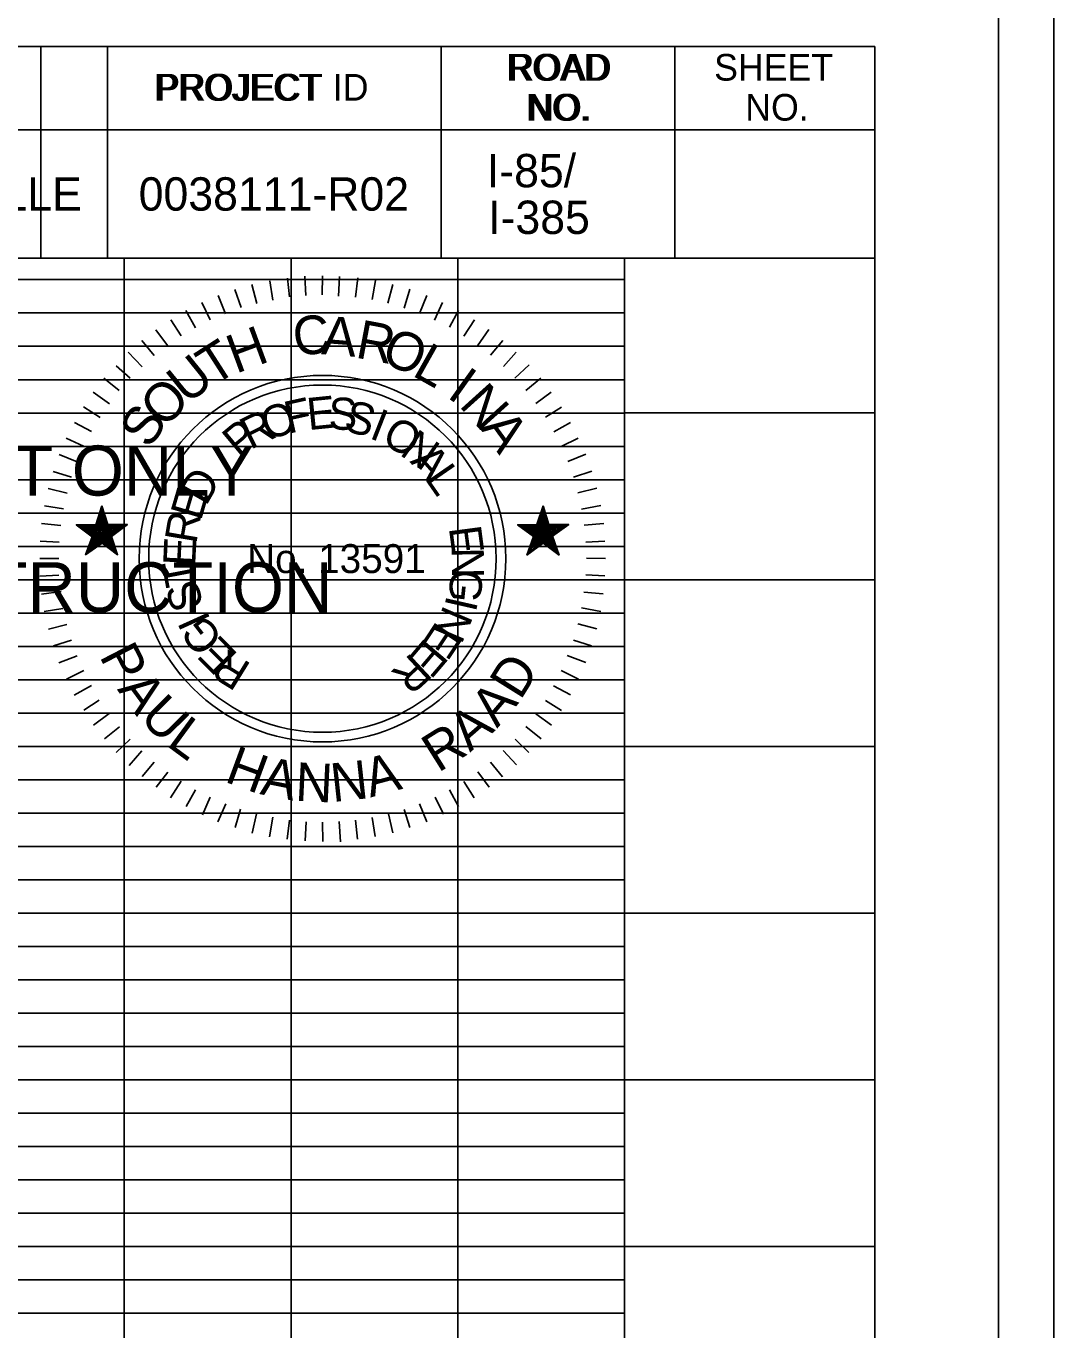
# Model space of a CAD drawing. Extents: x -3 to 42.6, y -1.4 to 22.8.
# Drawn here: x 30.206 to 33.287, y 16.75 to 20.66 of the extents above; entities that cross this region are included whole.
import ezdxf

# ---------------------------------------------------------------- set-up
doc = ezdxf.new("R2010")
doc.units = 0
for name, color, linetype in [('Level 1', 7, 'Continuous'), ('Level 2', 7, 'Continuous'), ('Level 3', 7, 'Continuous'), ('RD_SHT_Bndy', 7, 'Continuous'), ('RD_SHT_IplotShp', 7, 'Continuous'), ('RD_SHT_MjGrid', 7, 'Continuous'), ('RD_SHT_MnGrid', 7, 'Continuous'), ('RD_SHT_SEAL_DR', 7, 'Continuous'), ('RD_SHT_Snap', 7, 'Continuous'), ('RD_SHT_TX', 7, 'Continuous'), ('RD_Sketch10', 7, 'Continuous')]:
    doc.layers.add(name, color=color, linetype=linetype)

msp = doc.modelspace()

# ---------------------------------------------------------------- linework, layer by layer
at = {"layer": 'Level 1'}
for p, q in [((30.25, 20.5993), (30.25, 19.9643)), ((31.45, 20.5994), (31.45, 19.9644)), ((32.15, 20.5994), (32.15, 19.9644)), ((27.75, 20.3493), (32.75, 20.3494)), ((27.75, 19.9643), (32.75, 19.9644))]:
    msp.add_line(p, q, dxfattribs=at)
msp.add_lwpolyline([(-0.75, -0.4), (-0.75, 20.5995), (32.75, 20.5994), (32.7499, -0.4), (-0.75, -0.4)], dxfattribs=at)
at = {"layer": 'Level 2'}
for p, q in [((30.5, 0), (30.5, 19.9644)), ((31, 0), (31, 19.9644)), ((31.5, 0), (31.5, 19.9644)), ((32, 0), (32, 19.9644)), ((-0.75, 19), (32.75, 18.9999)), ((-0.75, 18), (32.75, 17.9999)), ((-0.75, 17), (32.75, 16.9999))]:
    msp.add_line(p, q, dxfattribs=at)
at = {"layer": 'Level 3'}
for p, q in [((0, 19.9), (32, 19.8999)), ((0, 19.8), (32, 19.7999)), ((0, 19.7), (32, 19.6999)), ((0, 19.6), (32, 19.5999)), ((0, 19.5), (32, 19.4999)), ((32, 19.5), (32.7499, 19.5)), ((0, 19.4), (32, 19.3999)), ((0, 19.3), (32, 19.2999)), ((0, 19.2), (32, 19.1999)), ((0, 19.1), (32, 19.0999)), ((0, 18.9), (32, 18.8999)), ((0, 18.8), (32, 18.7999)), ((0, 18.7), (32, 18.6999)), ((0, 18.6), (32, 18.5999)), ((0, 18.5), (32, 18.4999)), ((32, 18.5), (32.7499, 18.5)), ((0, 18.4), (32, 18.3999)), ((0, 18.3), (32, 18.2999)), ((0, 18.2), (32, 18.1999)), ((0, 18.1), (32, 18.0999)), ((0, 17.9), (32, 17.8999)), ((0, 17.8), (32, 17.7999)), ((0, 17.7), (32, 17.6999)), ((0, 17.6), (32, 17.5999)), ((0, 17.5), (32, 17.4999)), ((32, 17.5), (32.7499, 17.5)), ((0, 17.4), (32, 17.3999)), ((0, 17.3), (32, 17.2999)), ((0, 17.2), (32, 17.1999)), ((0, 17.1), (32, 17.0999)), ((0, 16.9), (32, 16.8999)), ((0, 16.8), (32, 16.7999))]:
    msp.add_line(p, q, dxfattribs=at)
at = {"layer": 'RD_SHT_Bndy'}
for p, q in [((30.45, 20.5994), (30.45, 19.9644)), ((31.45, 20.5994), (31.45, 19.9644)), ((32.15, 20.5994), (32.15, 19.9644)), ((28.85, 20.3493), (32.75, 20.3494)), ((28.85, 19.9643), (32.75, 19.9644))]:
    msp.add_line(p, q, dxfattribs=at)
msp.add_lwpolyline([(-0.75, -0.4), (-0.75, 20.5995), (32.75, 20.5994), (32.7499, -0.4), (-0.75, -0.4)], dxfattribs=at)
at = {"layer": 'RD_SHT_IplotShp'}
msp.add_lwpolyline([(-2.8793, 21.0836), (33.1207, 21.0836), (33.1207, -0.9164), (-2.8793, -0.9164)], close=True, dxfattribs=at)
at = {"layer": 'RD_SHT_MjGrid'}
for p, q in [((30.5, 0), (30.5, 19.9644)), ((31, 0), (31, 19.9644)), ((31.5, 0), (31.5, 19.9644)), ((32, 0), (32, 19.9644)), ((-0.75, 19), (32.75, 18.9999)), ((-0.75, 18), (32.75, 17.9999)), ((-0.75, 17), (32.75, 16.9999))]:
    msp.add_line(p, q, dxfattribs=at)
at = {"layer": 'RD_SHT_MnGrid'}
for p, q in [((0, 19.9), (32, 19.8999)), ((0, 19.8), (32, 19.7999)), ((0, 19.7), (32, 19.6999)), ((0, 19.6), (32, 19.5999)), ((0, 19.5), (32, 19.4999)), ((32, 19.5), (32.7499, 19.5)), ((0, 19.4), (32, 19.3999)), ((0, 19.3), (32, 19.2999)), ((0, 19.2), (32, 19.1999)), ((0, 19.1), (32, 19.0999)), ((0, 18.9), (32, 18.8999)), ((0, 18.8), (32, 18.7999)), ((0, 18.7), (32, 18.6999)), ((0, 18.6), (32, 18.5999)), ((0, 18.5), (32, 18.4999)), ((32, 18.5), (32.7499, 18.5)), ((0, 18.4), (32, 18.3999)), ((0, 18.3), (32, 18.2999)), ((0, 18.2), (32, 18.1999)), ((0, 18.1), (32, 18.0999)), ((0, 17.9), (32, 17.8999)), ((0, 17.8), (32, 17.7999)), ((0, 17.7), (32, 17.6999)), ((0, 17.6), (32, 17.5999)), ((0, 17.5), (32, 17.4999)), ((32, 17.5), (32.7499, 17.5)), ((0, 17.4), (32, 17.3999)), ((0, 17.3), (32, 17.2999)), ((0, 17.2), (32, 17.1999)), ((0, 17.1), (32, 17.0999)), ((0, 16.9), (32, 16.8999)), ((0, 16.8), (32, 16.7999))]:
    msp.add_line(p, q, dxfattribs=at)
at = {"layer": 'RD_SHT_SEAL_DR'}
for p, q in [((30.989, 19.9044), (30.9955, 19.8482)), ((31.0409, 19.9099), (31.0441, 19.8526)), ((31.0948, 19.9109), (31.0938, 19.8548)), ((31.1456, 19.9098), (31.1424, 19.8504)), ((31.2007, 19.9054), (31.1931, 19.8472)), ((30.8313, 19.8699), (30.8508, 19.8159)), ((30.8821, 19.885), (30.8972, 19.8288)), ((30.9361, 19.8968), (30.9458, 19.8385)), ((31.2536, 19.8969), (31.2428, 19.8407)), ((31.3055, 19.885), (31.2904, 19.8289)), ((31.3562, 19.8709), (31.3389, 19.8148)), ((30.7331, 19.8309), (30.7579, 19.7791)), ((30.7816, 19.8526), (30.8032, 19.7974)), ((31.407, 19.8526), (31.3854, 19.7986)), ((31.4545, 19.8309), (31.4296, 19.7781)), ((30.6845, 19.8073), (30.7136, 19.7554)), ((31.5021, 19.8073), (31.4751, 19.7575)), ((30.5948, 19.7489), (30.6294, 19.7024)), ((30.6401, 19.7791), (30.6704, 19.7316)), ((31.5496, 19.7791), (31.5182, 19.7305)), ((31.5928, 19.7499), (31.5593, 19.7014)), ((30.5527, 19.7175), (30.5894, 19.6722)), ((31.6348, 19.7176), (31.5981, 19.6733)), ((30.5116, 19.6819), (30.5537, 19.6388)), ((31.6748, 19.6819), (31.637, 19.6398)), ((30.4761, 19.6419), (30.5181, 19.6042)), ((31.7136, 19.6442), (31.6705, 19.6042)), ((30.4393, 19.6042), (30.4847, 19.5674)), ((31.7483, 19.6042), (31.704, 19.5674)), ((30.4069, 19.562), (30.4555, 19.5274)), ((31.7796, 19.562), (31.7342, 19.5285)), ((30.3777, 19.5189), (30.4274, 19.4864)), ((31.8109, 19.5178), (31.7623, 19.4875)), ((30.3507, 19.4714), (30.4015, 19.4443)), ((31.8379, 19.4714), (31.7882, 19.4433)), ((30.3259, 19.4249), (30.3777, 19.4)), ((31.8606, 19.4249), (31.8098, 19.399)), ((30.3054, 19.3752), (30.3594, 19.3536)), ((31.8832, 19.3763), (31.8293, 19.3547)), ((30.2871, 19.3244), (30.3421, 19.3072)), ((31.9016, 19.3255), (31.8466, 19.3072)), ((30.2719, 19.2737), (30.3291, 19.2596)), ((31.9167, 19.2748), (31.8596, 19.2607)), ((30.2611, 19.2218), (30.3183, 19.2121)), ((31.9286, 19.2229), (31.8703, 19.2111)), ((30.2525, 19.1689), (30.3097, 19.1624)), ((31.9372, 19.1689), (31.8789, 19.1635)), ((30.2481, 19.1159), (30.3054, 19.1128)), ((31.9405, 19.116), (31.8832, 19.1128)), ((30.2471, 19.0631), (30.3043, 19.0631)), ((31.9426, 19.0631), (31.8854, 19.0642)), ((30.2471, 19.0101), (30.3043, 19.0134)), ((31.9406, 19.0113), (31.8833, 19.0145)), ((30.2525, 18.9562), (30.3108, 18.9648)), ((31.9351, 18.9572), (31.8779, 18.9626)), ((30.2601, 18.9044), (30.3162, 18.9141)), ((31.9286, 18.9044), (31.8703, 18.9152)), ((30.273, 18.8514), (30.3281, 18.8654)), ((31.9167, 18.8525), (31.8596, 18.8676)), ((30.2881, 18.8018), (30.3421, 18.819)), ((31.9006, 18.8018), (31.8466, 18.819)), ((30.3043, 18.751), (30.3594, 18.7715)), ((31.8832, 18.7521), (31.8281, 18.7726)), ((30.327, 18.7013), (30.3789, 18.7272)), ((31.8617, 18.7013), (31.8098, 18.7273)), ((30.3496, 18.6538), (30.4016, 18.6829)), ((31.8379, 18.6549), (31.7871, 18.6819)), ((30.3788, 18.6084), (30.4253, 18.6387)), ((31.811, 18.6074), (31.7623, 18.6375)), ((30.408, 18.5641), (30.4545, 18.5987)), ((31.7806, 18.5642), (31.7342, 18.5977)), ((30.4404, 18.5231), (30.4858, 18.5587)), ((31.7493, 18.5231), (31.7041, 18.5598)), ((30.4761, 18.482), (30.5181, 18.522)), ((31.7126, 18.4821), (31.6716, 18.522)), ((30.5149, 18.4432), (30.5527, 18.4864)), ((31.6759, 18.4443), (31.636, 18.4874)), ((30.5538, 18.4097), (30.5895, 18.4529)), ((30.5959, 18.3773), (30.6305, 18.4227)), ((31.5938, 18.3773), (31.5604, 18.4238)), ((31.6338, 18.4086), (31.5981, 18.4529)), ((30.6391, 18.3459), (30.6705, 18.3957)), ((31.5485, 18.346), (31.5182, 18.3946)), ((30.6856, 18.32), (30.7136, 18.3697)), ((30.7342, 18.2952), (30.7579, 18.3481)), ((31.4567, 18.2963), (31.4318, 18.3482)), ((31.5021, 18.32), (31.4751, 18.3698)), ((30.7806, 18.2736), (30.8043, 18.3276)), ((30.8324, 18.2563), (30.8486, 18.3114)), ((31.3562, 18.2563), (31.339, 18.3103)), ((31.407, 18.2736), (31.3854, 18.3276)), ((30.8831, 18.2401), (30.8962, 18.2974)), ((30.9351, 18.2293), (30.9459, 18.2877)), ((30.988, 18.2218), (30.9956, 18.279)), ((31.042, 18.2164), (31.0451, 18.2736)), ((31.0949, 18.2153), (31.0948, 18.2725)), ((31.1478, 18.2142), (31.1446, 18.2747)), ((31.1996, 18.2218), (31.1931, 18.279)), ((31.2526, 18.2294), (31.2428, 18.2865)), ((31.3055, 18.2412), (31.2926, 18.2974))]:
    msp.add_line(p, q, dxfattribs=at)
for points in [[(30.4329, 19.2219), (30.4145, 19.1646), (30.3562, 19.1646), (30.4036, 19.1289), (30.3842, 19.0749), (30.4339, 19.1095), (30.4803, 19.0749), (30.462, 19.13), (30.5096, 19.1656), (30.4512, 19.1657)], [(30.4318, 19.2132), (30.4166, 19.1635), (30.3626, 19.1635), (30.4048, 19.1311), (30.3896, 19.0804), (30.4317, 19.1128), (30.4749, 19.0804), (30.4588, 19.1322), (30.503, 19.1624), (30.4501, 19.1634)], [(30.4339, 19.2056), (30.4166, 19.1603), (30.3702, 19.1603), (30.4091, 19.1322), (30.3951, 19.0869), (30.4329, 19.1149), (30.4717, 19.0858), (30.4555, 19.1334), (30.4955, 19.1592), (30.4479, 19.1603)], [(31.7559, 19.2219), (31.7364, 19.1657), (31.6791, 19.1646), (31.7266, 19.13), (31.7072, 19.0739), (31.7558, 19.1095), (31.8034, 19.0739), (31.7839, 19.1301), (31.8325, 19.1657), (31.7731, 19.1658)], [(31.7548, 19.2143), (31.7386, 19.1635), (31.6856, 19.1624), (31.7299, 19.1301), (31.7137, 19.0804), (31.7558, 19.1106), (31.7991, 19.0804), (31.7828, 19.1312), (31.826, 19.1635), (31.772, 19.1624)], [(31.7558, 19.2056), (31.7418, 19.1592), (31.6932, 19.1603), (31.7321, 19.1322), (31.718, 19.0858), (31.7558, 19.1149), (31.7947, 19.0869), (31.7796, 19.1312), (31.8185, 19.1614), (31.771, 19.1603)], [(30.4339, 19.198), (30.4188, 19.1581), (30.3777, 19.157), (30.4123, 19.1333), (30.3993, 19.0934), (30.4317, 19.1181), (30.4674, 19.0934), (30.4555, 19.1334), (30.4879, 19.1592), (30.4458, 19.1571)], [(30.4329, 19.1905), (30.422, 19.1559), (30.3852, 19.1549), (30.4145, 19.1344), (30.4026, 19.0988), (30.4328, 19.1214), (30.4631, 19.0988), (30.4512, 19.1344), (30.4793, 19.1559), (30.4458, 19.156)], [(30.4329, 19.183), (30.4241, 19.1527), (30.3929, 19.1539), (30.4177, 19.1354), (30.408, 19.1063), (30.4339, 19.1246), (30.4587, 19.1052), (30.448, 19.1354), (30.4739, 19.1516), (30.4426, 19.1527)], [(30.4328, 19.1744), (30.4252, 19.1517), (30.4004, 19.1484), (30.421, 19.1365), (30.4134, 19.1128), (30.4317, 19.1268), (30.4544, 19.1117), (30.4469, 19.1365), (30.4652, 19.1506), (30.4404, 19.1506)], [(30.4328, 19.1667), (30.4275, 19.1484), (30.408, 19.1484), (30.4242, 19.1376), (30.4177, 19.1193), (30.4329, 19.129), (30.4491, 19.1182), (30.4436, 19.1365), (30.4587, 19.1474), (30.4382, 19.1494)], [(31.7548, 19.1981), (31.7428, 19.157), (31.7007, 19.157), (31.7364, 19.1333), (31.7201, 19.0944), (31.7558, 19.1182), (31.7893, 19.0944), (31.7763, 19.1333), (31.8109, 19.1581), (31.7688, 19.1581)], [(31.7547, 19.1894), (31.744, 19.1549), (31.7072, 19.156), (31.7364, 19.1354), (31.7266, 19.0987), (31.7547, 19.1203), (31.7839, 19.0998), (31.7741, 19.1333), (31.8044, 19.1549), (31.7666, 19.1559)], [(31.7569, 19.1819), (31.7461, 19.1538), (31.7148, 19.1538), (31.7407, 19.1365), (31.7299, 19.1052), (31.7558, 19.1236), (31.7796, 19.1063), (31.7721, 19.1344), (31.7947, 19.1528), (31.7656, 19.1539)], [(31.7558, 19.1744), (31.7471, 19.1516), (31.7223, 19.1506), (31.7439, 19.1354), (31.7353, 19.1127), (31.7558, 19.1279), (31.7752, 19.1117), (31.7676, 19.1365), (31.7893, 19.1506), (31.7634, 19.1517)], [(31.7558, 19.1657), (31.7505, 19.1484), (31.7299, 19.1484), (31.7461, 19.1365), (31.7396, 19.1193), (31.7558, 19.1289), (31.771, 19.1182), (31.7656, 19.1365), (31.7796, 19.1484), (31.7612, 19.1484)], [(30.4328, 19.1581), (30.4285, 19.1463), (30.4145, 19.1463), (30.4252, 19.1376), (30.4231, 19.1257), (30.4339, 19.1333), (30.4426, 19.1246), (30.4404, 19.1376), (30.4512, 19.1452), (30.4371, 19.1463)], [(30.4339, 19.1517), (30.4296, 19.1441), (30.4231, 19.1441), (30.4296, 19.1386), (30.4263, 19.1311), (30.4339, 19.1365), (30.4382, 19.1311), (30.4361, 19.1398), (30.4426, 19.1429), (30.4361, 19.143)], [(30.4339, 19.1429), (30.4328, 19.1398), (30.4286, 19.1409), (30.4317, 19.1409), (30.4307, 19.1376), (30.4329, 19.1376), (30.434, 19.1376), (30.4339, 19.1398), (30.4371, 19.1419), (30.4339, 19.1419)], [(31.7558, 19.1592), (31.7493, 19.1462), (31.7386, 19.1452), (31.7482, 19.1387), (31.7439, 19.1257), (31.7558, 19.1322), (31.7666, 19.1246), (31.7623, 19.1365), (31.7742, 19.1452), (31.7612, 19.1463)], [(31.7548, 19.1517), (31.7537, 19.1441), (31.745, 19.144), (31.7526, 19.1387), (31.7483, 19.1311), (31.7569, 19.1354), (31.7623, 19.1311), (31.7591, 19.1376), (31.7666, 19.144), (31.7591, 19.1429)], [(31.7569, 19.143), (31.7558, 19.1409), (31.7526, 19.1409), (31.7536, 19.1398), (31.7537, 19.1365), (31.7548, 19.1387), (31.7581, 19.1387), (31.7569, 19.1398), (31.758, 19.1409), (31.7558, 19.1398)]]:
    msp.add_lwpolyline(points, close=True, dxfattribs=at)
for radius in [0.5496, 0.5207]:
    msp.add_circle((31.0942, 19.0631), radius, dxfattribs=at)
at = {"layer": 'RD_SHT_Snap'}
msp.add_lwpolyline([(-2.7133, 21.0836), (33.2866, 21.0836), (33.2866, -0.9164), (-2.7133, -0.9164)], close=True, dxfattribs=at)

# ---------------------------------------------------------------- texts
at = {"layer": 'Level 1'}
for s, p in [('ROAD', (31.6446, 20.4968)), ('SHEET', (32.2682, 20.4968)), ('PROJECT', (30.5889, 20.4368)), ('NO.', (31.7038, 20.3768)), ('NO.', (32.3615, 20.3768))]:
    msp.add_text(s, height=0.08, rotation=0.0013, dxfattribs=at).set_placement(p)
at = {"layer": 'RD_SHT_SEAL_DR'}
for s, height, rotation, p in [('C', 0.1157, 7.9045, (31.0138, 19.6689)), ('A', 0.1157, 355.5041, (31.0895, 19.6765)), ('H', 0.1157, 20.3049, (30.8346, 19.6171)), ('R', 0.1157, 349.3039, (31.1899, 19.6668)), ('O', 0.1157, 336.9035, (31.2645, 19.6549)), ('T', 0.1157, 32.7054, (30.7666, 19.5783)), ('U', 0.1157, 38.9056, (30.6887, 19.5231)), ('L', 0.1157, 330.7033, (31.3595, 19.6139)), ('I', 0.1157, 324.5031, (31.4642, 19.5491)), ('O', 0.1157, 45.1058, (30.6186, 19.4508)), ('N', 0.1157, 312.1026, (31.501, 19.5221)), ('S', 0.1157, 57.5062, (30.5765, 19.3892)), ('O', 0.0963, 19.3187, (30.93, 19.4161)), ('F', 0.0963, 12.5331, (30.9919, 19.4374)), ('E', 0.0963, 5.7476, (31.0521, 19.4484)), ('S', 0.0963, 358.962, (31.1119, 19.4504)), ('S', 0.0963, 345.3909, (31.1543, 19.4479)), ('P', 0.0963, 39.6753, (30.8458, 19.3605)), ('R', 0.0963, 26.1042, (30.8781, 19.3887)), ('I', 0.0963, 338.6054, (31.2315, 19.4255)), ('O', 0.0963, 331.8198, (31.2676, 19.4099)), ('A', 0.1157, 305.9024, (31.5646, 19.4551)), ('N', 0.0963, 325.0343, (31.3223, 19.3764)), ('A', 0.0963, 311.4632, (31.3546, 19.3538)), ('D', 0.0964, 60.0967, (30.7449, 19.2186)), ('L', 0.0963, 304.6776, (31.3991, 19.3036)), ('E', 0.0964, 73.6728, (30.7298, 19.1744)), ('R', 0.0964, 80.4609, (30.7158, 19.1052)), ('E', 0.0963, 277.5354, (31.4728, 19.1559)), ('E', 0.0964, 87.249, (30.7126, 19.0393)), ('No. 13591', 0.08672, 0.0004, (30.8686, 19.0199)), ('N', 0.0963, 270.7499, (31.4814, 19.0964)), ('T', 0.0964, 100.8252, (30.7211, 18.9897)), ('G', 0.0963, 263.9643, (31.4812, 19.0364)), ('S', 0.0964, 107.6133, (30.7396, 18.9238)), ('I', 0.0963, 257.1788, (31.4673, 18.9559)), ('I', 0.0964, 114.4014, (30.7601, 18.8794)), ('N', 0.0963, 246.8176, (31.4586, 18.927)), ('G', 0.0964, 127.9775, (30.8001, 18.8223)), ('E', 0.0963, 236.4563, (31.4371, 18.8789)), ('P', 0.1157, 297.3177, (30.4242, 18.7712)), ('E', 0.0964, 134.7656, (30.8443, 18.7747)), ('E', 0.0963, 229.6708, (31.4029, 18.8279)), ('R', 0.0964, 148.3418, (30.8843, 18.7456)), ('R', 0.0963, 222.8852, (31.3627, 18.7834)), ('D', 0.1157, 58.0167, (31.6873, 18.636)), ('A', 0.1157, 306.2426, (30.4776, 18.6708)), ('U', 0.1157, 314.7425, (30.5424, 18.584)), ('A', 0.1157, 49.5168, (31.6176, 18.553)), ('L', 0.1157, 323.6675, (30.6234, 18.5042)), ('A', 0.1157, 41.0169, (31.5365, 18.4813)), ('R', 0.1157, 32.0919, (31.4409, 18.4197)), ('H', 0.1157, 339.8173, (30.7974, 18.3953)), ('A', 0.1157, 348.7423, (30.9046, 18.3573)), ('N', 0.1157, 6.1671, (31.1247, 18.3329)), ('A', 0.1157, 15.0921, (31.2376, 18.3465)), ('N', 0.1157, 357.2422, (31.011, 18.337))]:
    msp.add_text(s, height=height, rotation=rotation, dxfattribs=at).set_placement(p)
at = {"layer": 'RD_SHT_TX'}
for s, p in [('ROAD', (31.6522, 20.4968)), ('SHEET', (32.2682, 20.4968)), ('PROJECT ID', (30.5963, 20.4368)), ('NO.', (31.7115, 20.3768)), ('NO.', (32.3615, 20.3768))]:
    msp.add_text(s, height=0.08, rotation=0.0013, dxfattribs=at).set_placement(p)
for s, p in [('I-85/', (31.587, 20.1769)), ('GREENVILLE', (29.533, 20.1068)), ('0038111-R02', (30.5433, 20.1069)), ('I-385', (31.5909, 20.0369))]:
    msp.add_text(s, height=0.1, dxfattribs=at).set_placement(p)
at = {"layer": 'RD_Sketch10'}
for s, p in [('FZJV CONCEPT ONLY', (28.7717, 19.2523)), ('NOT FOR CONSTRUCTION', (28.5497, 18.9023))]:
    msp.add_text(s, height=0.15, dxfattribs=at).set_placement(p)

doc.saveas('drawing.dxf')
